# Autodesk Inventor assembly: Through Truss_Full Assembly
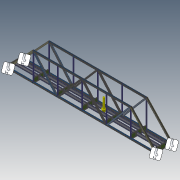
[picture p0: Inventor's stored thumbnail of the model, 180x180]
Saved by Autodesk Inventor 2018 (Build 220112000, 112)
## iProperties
Created: 2018-02
Part Number: Through Truss_Full Assembly
Document SubType Name: Assembly
Designer: STK
Mass: 1.33321e+07 g
Surface Area: 3.07047e+06 cm^2
Volume: 1.69835e+06 cm^3
Density: 7.85 g/cm^3
Author: STK
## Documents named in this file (31)
- D:\SolidWorks\Through Truss\Through Truss_Full Assembly.iam
- D:\SolidWorks\Through Truss\Interior Floor Beam\Interior Floor Beam.iam
- D:\SolidWorks\Through Truss\L1U1\L1U1.iam
- D:\SolidWorks\Through Truss\L2L3.iam
- D:\SolidWorks\Through Truss\L0U1 Plate.ipt
- D:\SolidWorks\Through Truss\L0U1 Plate_Mirrored.ipt
- D:\SolidWorks\Through Truss\L0U1_Connecting Plate.ipt
- D:\SolidWorks\Through Truss\L0U1_Connecting Plate_Mirrored.ipt
- D:\SolidWorks\Through Truss\L2U1_C Channel.ipt
- D:\SolidWorks\Through Truss\L2U1_C Channel_Mirrored.ipt
- D:\SolidWorks\Through Truss\L2U3 C channel.ipt
- D:\SolidWorks\Through Truss\L2U3 C channel_Mirrored.ipt
- D:\SolidWorks\Through Truss\Floor Beam_End\Floor Beam End.iam
- D:\SolidWorks\Through Truss\Rail Girder\Rail Girder.iam
- D:\SolidWorks\Through Truss\Cover Plate_Bearing End.ipt
- D:\SolidWorks\Through Truss\Cover Plate_End Raker End.ipt
- D:\SolidWorks\Through Truss\Cover Plate Top Cords.ipt
- D:\SolidWorks\Through Truss\L2U1_C Channel_MIR.ipt
- D:\SolidWorks\Through Truss\L2U1_C Channel_Mirrored_MIR.ipt
- D:\SolidWorks\Through Truss\L2U3 C channel_MIR.ipt
- D:\SolidWorks\Through Truss\L2U3 C channel_Mirrored_MIR.ipt
- D:\SolidWorks\Through Truss\L0U1 Plate_Mirrored_MIR.ipt
- D:\SolidWorks\Through Truss\L0U1_Connecting Plate_MIR.ipt
- D:\SolidWorks\Through Truss\L0U1_Connecting Plate_Mirrored_MIR.ipt
- D:\SolidWorks\Through Truss\L0U1 Plate_MIR.ipt
- D:\SolidWorks\Through Truss\Cover Plate_Bearing End_MIR.ipt
- D:\SolidWorks\Through Truss\Cover Plate_End Raker End_MIR.ipt
- D:\SolidWorks\Through Truss\Rail Girder\Angle 6 x 6 for rivetting.ipt
- D:\SolidWorks\Through Truss\Rail Girder\Plate For Riveting\Plate For Riveting-02.ipt
- D:\SolidWorks\Through Truss\Rail Girder\Plate For Riveting.ipt
- D:\SolidWorks\Through Truss\Connecting Plate For Riveting.ipt
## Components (175 placed, 29 different names)
1. Interior Floor Beam:1 [sub-assembly] — Mate:5, Mate:6, Flush:2, Flush:5, Flush:6, Mate:7, Flush:8, Flush:9, Mate:9, Flush:10, Mate:39, Mate:54, Mate:56
2. L1U1:1 [sub-assembly] — Flush:6, Flush:7, Mate:7, Flush:13
3. L2L3:1 [sub-assembly] — Flush:9, Mate:9, Flush:10, Flush:11, Flush:12, Mate:11, Mate:13, Flush:30, Mate:27, Flush:31, Mate:33, Mate:60
4. L2L3:2 [sub-assembly] — Flush:11, Mate:10, Flush:12, Mate:14, Flush:14, Flush:15, Mate:23, Mate:24, Mate:26, Flush:28, Mate:61
5. L1U1:2 [sub-assembly] — Mate:12, Mate:13, Flush:13, Flush:18, Flush:19, Mate:59
6. Interior Floor Beam:2 [sub-assembly] — Flush:2, Flush:5, Mate:10, Mate:11, Mate:12, Flush:17, Angle:1, Flush:32, Mate:38, Mate:58
7. L2L3:3 [sub-assembly] — Mate:14, Flush:14, Flush:15, Mate:15, Flush:23, Flush:24, Mate:20, Mate:21, Flush:25, Flush:26, Flush:34, Flush:35, Mate:40
8. Interior Floor Beam:3 [sub-assembly] — Mate:15, Flush:17, Mate:16, Flush:32, Flush:33, Mate:36
9. L1U1:3 [sub-assembly] — Mate:16, Flush:18, Flush:19
10. L2L3:4 [sub-assembly] — Mate:28, Mate:34, Flush:39, Flush:40
11. L2L3:5 [sub-assembly] — Flush:21, Mate:19, Flush:22, Flush:27, Mate:25, Mate:41, Flush:36, Flush:37, Mate:44
12. L0U1 Plate_Mirrored:1 — Flush:21, Mate:19, Flush:22
13. L0U1_Connecting Plate:1 — Flush:23, Flush:24, Mate:20
14. L0U1_Connecting Plate_Mirrored:1 — Mate:21, Flush:25, Flush:26, Mate:35, Mate:43
15. L2U1_C Channel:1 — Mate:24, Flush:27, Mate:25, Flush:29
16. L2U1_C Channel_Mirrored:1 — Mate:26, Flush:28, Flush:29
17. L2U3 C channel:1 — Flush:30, Mate:27, Mate:28
18. L2U3 C channel_Mirrored:1 — Flush:31, Mate:33, Mate:34
19. Floor Beam End:1 [sub-assembly] — Flush:33, Mate:35, Mate:36
20. Cover Plate_Bearing End:1 — Flush:34, Flush:35, Mate:40
21. Cover Plate_End Raker End:1 — Mate:42, Flush:38, Mate:43
22. L0U1 Plate:1 — Mate:41, Flush:36, Flush:37, Mate:42, Flush:38
23. Cover Plate Top Cords:1 — Mate:44, Flush:39, Flush:40
24. Rail Girder:4 [sub-assembly] — Mate:45
25. Rail Girder:5 [sub-assembly]
26. Rail Girder:6 [sub-assembly] — Mate:50, Flush:53, Mate:51, Mate:52, Mate:53
27. L2L3:6 [sub-assembly] — Flush:41, Flush:42
28. L2L3:7 [sub-assembly] — Flush:41, Flush:42, Flush:43, Flush:44, Mate:46, Mate:47
29. L2L3:8 [sub-assembly] — Flush:43, Flush:44, Mate:46
30. L1U1:4 [sub-assembly] — Flush:45, Flush:46
31. L1U1:5 [sub-assembly] — Flush:46, Flush:47, Flush:48
32. L1U1:6 [sub-assembly] — Flush:47, Flush:48
33. L2L3:9 [sub-assembly] — Flush:50, Flush:51
34. L2L3:10 [sub-assembly] — Mate:48
35. Cover Plate Top Cords:2 — Flush:50, Flush:51, Mate:48
36. L2U1_C Channel_MIR:1 — Flush:52
37. L2U1_C Channel_Mirrored_MIR:1 — Flush:52
38. L2U3 C channel_MIR:1
39. L2U3 C channel_Mirrored_MIR:1
40. L0U1 Plate_Mirrored_MIR:1
41. L0U1_Connecting Plate_MIR:1
42. L0U1_Connecting Plate_Mirrored_MIR:1
43. L0U1 Plate_MIR:1
44. Cover Plate_Bearing End_MIR:1
45. Cover Plate_End Raker End_MIR:1
46. Plate For Riveting-02:4 — Flush:57, Flush:58
47. Plate For Riveting-02:3 — Flush:57, Flush:58
48. Plate For Riveting-02:2 — Mate:58, Flush:55, Flush:56
49. Plate For Riveting-02:1 — Mate:54, Mate:56, Mate:57, Flush:55, Flush:56
50. Connecting Plate For Riveting:3
51. Connecting Plate For Riveting:4
52. L1U1:7 [sub-assembly] — Mate:62, Flush:62
53. L2L3:11 [sub-assembly] — Mate:63, Flush:60, Flush:61, Mate:65, Flush:74, Mate:82, Flush:75, Mate:84, Mate:101
54. L2L3:12 [sub-assembly] — Flush:60, Mate:64, Flush:61, Flush:64, Flush:65, Mate:66, Mate:77, Flush:71, Mate:80, Flush:73, Mate:100
55. L1U1:8 [sub-assembly] — Flush:62, Mate:65, Flush:63, Flush:68, Flush:69, Mate:102
56. Interior Floor Beam:4 [sub-assembly] — Mate:63, Mate:64, Flush:63, Flush:66, Flush:67, Angle:2, Mate:86, Mate:99
57. L2L3:13 [sub-assembly] — Flush:64, Flush:65, Mate:66, Mate:67, Mate:71, Mate:72, Mate:73, Mate:74, Mate:75, Mate:76, Mate:87, Flush:79, Flush:80
58. Interior Floor Beam:5 [sub-assembly] — Flush:66, Flush:67, Mate:67, Flush:70, Mate:85, Flush:77
59. L1U1:9 [sub-assembly] — Flush:68, Flush:69, Flush:70
60. L2L3:14 [sub-assembly] — Mate:81, Mate:83, Flush:82, Flush:83
61. L2L3:15 [sub-assembly] — Mate:68, Mate:69, Mate:70, Mate:78, Mate:79, Mate:90, Mate:91, Mate:92, Mate:93
62. L0U1 Plate_Mirrored:2 — Mate:68, Mate:69, Mate:70
63. L0U1_Connecting Plate:2 — Mate:71, Mate:72, Mate:73
64. L0U1_Connecting Plate_Mirrored:2 — Mate:74, Mate:75, Mate:76, Flush:76, Mate:88
65. L2U1_C Channel:2 — Mate:78, Mate:79, Flush:71, Flush:72
66. L2U1_C Channel_Mirrored:2 — Flush:72, Mate:80, Flush:73
67. L2U3 C channel:2 — Mate:81, Flush:74, Mate:82
68. L2U3 C channel_Mirrored:2 — Mate:83, Flush:75, Mate:84
69. Floor Beam End:2 [sub-assembly] — Mate:85, Flush:76, Flush:77
70. Cover Plate_Bearing End:2 — Mate:87, Flush:79, Flush:80
71. Cover Plate_End Raker End:2 — Mate:88, Flush:81, Mate:89
72. L0U1 Plate:2 — Flush:81, Mate:89, Mate:90, Mate:91, Mate:92
73. Cover Plate Top Cords:3 — Flush:82, Flush:83, Mate:93
74. Rail Girder:8 [sub-assembly] — Flush:84
75. Rail Girder:9 [sub-assembly]
76. Rail Girder:10 [sub-assembly] — Flush:96, Mate:97, Flush:97, Mate:98, Flush:99
77. L2L3:16 [sub-assembly] — Flush:85, Flush:86
78. L2L3:17 [sub-assembly] — Flush:85, Flush:86, Mate:94, Flush:87, Flush:88, Mate:95
79. L2L3:18 [sub-assembly] — Mate:94, Flush:87, Flush:88
80. L1U1:10 [sub-assembly] — Flush:89, Flush:90
81. L1U1:11 [sub-assembly] — Flush:90, Flush:91, Flush:92
82. L1U1:12 [sub-assembly] — Flush:91, Flush:92
83. L2L3:19 [sub-assembly] — Flush:93, Flush:94
84. L2L3:20 [sub-assembly] — Mate:96
85. Cover Plate Top Cords:4 — Mate:96, Flush:93, Flush:94
86. L2U1_C Channel_MIR:2 — Flush:95
87. L2U1_C Channel_Mirrored_MIR:2 — Flush:95
88. L2U3 C channel_MIR:2
89. L2U3 C channel_Mirrored_MIR:2
90. L0U1 Plate_Mirrored_MIR:2
91. L0U1_Connecting Plate_MIR:2
92. L0U1_Connecting Plate_Mirrored_MIR:2
93. L0U1 Plate_MIR:2
94. Cover Plate_Bearing End_MIR:2
95. Cover Plate_End Raker End_MIR:2
96. Plate For Riveting-02:13 — Flush:100, Flush:101, Flush:102
97. Plate For Riveting-02:14 — Flush:101, Flush:102, Mate:99
98. Plate For Riveting-02:15 — Flush:103, Flush:104
99. Plate For Riveting-02:16 — Flush:103, Flush:104
100. Connecting Plate For Riveting:6
101. Connecting Plate For Riveting:7
102. Rail Girder:1 [sub-assembly] — Mate:37, Mate:38, Mate:39, Mate:57
103. Rail Girder:2 [sub-assembly]
104. Rail Girder:3 [sub-assembly]
105. Plate For Riveting-02:6
106. Plate For Riveting-02:5
107. Plate For Riveting-02:7
108. Plate For Riveting-02:8
109. Plate For Riveting-02:9
110. Plate For Riveting-02:10
111. Plate For Riveting-02:11
112. Plate For Riveting-02:12
113. Angle 6 x 6 for rivetting:1 — Mate:50, Flush:53, Mate:51, Flush:54
114. Angle 6 x 6 for rivetting:7
115. Angle 6 x 6 for rivetting:3
116. Angle 6 x 6 for rivetting:5 — Flush:59
117. Angle 6 x 6 for rivetting:2 — Mate:52, Mate:53, Flush:54
118. Angle 6 x 6 for rivetting:8
119. Angle 6 x 6 for rivetting:6 — Flush:59
120. Angle 6 x 6 for rivetting:4
121. Angle 6 x 6 for rivetting:9
122. Angle 6 x 6 for rivetting:10
123. Angle 6 x 6 for rivetting:11
124. Angle 6 x 6 for rivetting:12
125. Angle 6 x 6 for rivetting:13
126. Angle 6 x 6 for rivetting:14
127. Angle 6 x 6 for rivetting:15
128. Angle 6 x 6 for rivetting:16
129. Angle 6 x 6 for rivetting:17
130. Angle 6 x 6 for rivetting:18
131. Angle 6 x 6 for rivetting:19
132. Angle 6 x 6 for rivetting:20
133. Angle 6 x 6 for rivetting:21
134. Angle 6 x 6 for rivetting:22
135. Angle 6 x 6 for rivetting:23
136. Angle 6 x 6 for rivetting:24
137. Connecting Plate For Riveting:1 — Mate:59, Mate:60, Mate:61
138. Connecting Plate For Riveting:2
139. Rail Girder:7 [sub-assembly] — Mate:86, Flush:78, Flush:100
140. Rail Girder:11 [sub-assembly]
141. Rail Girder:12 [sub-assembly]
142. Plate For Riveting-02:17
143. Plate For Riveting-02:18
144. Plate For Riveting-02:21
145. Plate For Riveting-02:22
146. Plate For Riveting-02:19
147. Plate For Riveting-02:20
148. Plate For Riveting-02:23
149. Plate For Riveting-02:24
150. Angle 6 x 6 for rivetting:25 — Flush:96, Mate:97, Flush:97, Flush:98
151. Angle 6 x 6 for rivetting:26
152. Angle 6 x 6 for rivetting:27
153. Angle 6 x 6 for rivetting:28 — Flush:105
154. Angle 6 x 6 for rivetting:29 — Flush:98, Mate:98, Flush:99
155. Angle 6 x 6 for rivetting:30
156. Angle 6 x 6 for rivetting:31 — Flush:105
157. Angle 6 x 6 for rivetting:32
158. Angle 6 x 6 for rivetting:33
159. Angle 6 x 6 for rivetting:34
160. Angle 6 x 6 for rivetting:35
161. Angle 6 x 6 for rivetting:36
162. Angle 6 x 6 for rivetting:37
163. Angle 6 x 6 for rivetting:38
164. Angle 6 x 6 for rivetting:39
165. Angle 6 x 6 for rivetting:40
166. Angle 6 x 6 for rivetting:41
167. Angle 6 x 6 for rivetting:42
168. Angle 6 x 6 for rivetting:43
169. Angle 6 x 6 for rivetting:44
170. Angle 6 x 6 for rivetting:45
171. Angle 6 x 6 for rivetting:46
172. Angle 6 x 6 for rivetting:47
173. Angle 6 x 6 for rivetting:48
174. Connecting Plate For Riveting:5 — Mate:100, Mate:101, Mate:102
175. Connecting Plate For Riveting:8
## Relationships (189: Flush 99, Mate 88, Angle 2)
- Mate:5: Interior Floor Beam:1
- Mate:6: Interior Floor Beam:1
- Flush:2: Interior Floor Beam:1 ↔ Interior Floor Beam:2
- Flush:5: Interior Floor Beam:1 ↔ Interior Floor Beam:2
- Flush:6: Interior Floor Beam:1 ↔ L1U1:1
- Flush:7: L1U1:1
- Mate:7: Interior Floor Beam:1 ↔ L1U1:1
- Flush:8: Interior Floor Beam:1
- Flush:9: Interior Floor Beam:1 ↔ L2L3:1
- Mate:9: Interior Floor Beam:1 ↔ L2L3:1
- Flush:10: Interior Floor Beam:1 ↔ L2L3:1
- Flush:11: L2L3:1 ↔ L2L3:2
- Mate:10: L2L3:2 ↔ Interior Floor Beam:2
- Flush:12: L2L3:1 ↔ L2L3:2
- Mate:11: L2L3:1 ↔ Interior Floor Beam:2
- Mate:12: L1U1:2 ↔ Interior Floor Beam:2
- Mate:13: L2L3:1 ↔ L1U1:2
- Flush:13: L1U1:1 ↔ L1U1:2
- Mate:14: L2L3:2 ↔ L2L3:3
- Flush:14: L2L3:2 ↔ L2L3:3
- Flush:15: L2L3:2 ↔ L2L3:3
- Mate:15: L2L3:3 ↔ Interior Floor Beam:3
- Flush:17: Interior Floor Beam:2 ↔ Interior Floor Beam:3
- Mate:16: Interior Floor Beam:3 ↔ L1U1:3
- Flush:18: L1U1:2 ↔ L1U1:3
- Flush:19: L1U1:2 ↔ L1U1:3
- Flush:21: L2L3:5 ↔ L0U1 Plate_Mirrored:1
- Mate:19: L2L3:5 ↔ L0U1 Plate_Mirrored:1
- Flush:22: L2L3:5 ↔ L0U1 Plate_Mirrored:1
- Flush:23: L2L3:3 ↔ L0U1_Connecting Plate:1
- Flush:24: L2L3:3 ↔ L0U1_Connecting Plate:1
- Mate:20: L2L3:3 ↔ L0U1_Connecting Plate:1
- Mate:21: L2L3:3 ↔ L0U1_Connecting Plate_Mirrored:1
- Flush:25: L2L3:3 ↔ L0U1_Connecting Plate_Mirrored:1
- Flush:26: L2L3:3 ↔ L0U1_Connecting Plate_Mirrored:1
- Mate:23: L2L3:2
- Angle:1: Interior Floor Beam:2
- Mate:24: L2L3:2 ↔ L2U1_C Channel:1
- Flush:27: L2L3:5 ↔ L2U1_C Channel:1
- Mate:25: L2L3:5 ↔ L2U1_C Channel:1
- Mate:26: L2L3:2 ↔ L2U1_C Channel_Mirrored:1
- Flush:28: L2L3:2 ↔ L2U1_C Channel_Mirrored:1
- Flush:29: L2U1_C Channel:1 ↔ L2U1_C Channel_Mirrored:1
- Flush:30: L2L3:1 ↔ L2U3 C channel:1
- Mate:27: L2L3:1 ↔ L2U3 C channel:1
- Mate:28: L2L3:4 ↔ L2U3 C channel:1
- Flush:31: L2L3:1 ↔ L2U3 C channel_Mirrored:1
- Mate:33: L2L3:1 ↔ L2U3 C channel_Mirrored:1
- Mate:34: L2L3:4 ↔ L2U3 C channel_Mirrored:1
- Flush:32: Interior Floor Beam:2 ↔ Interior Floor Beam:3
- Flush:33: Interior Floor Beam:3 ↔ Floor Beam End:1
- Mate:35: L0U1_Connecting Plate_Mirrored:1 ↔ Floor Beam End:1
- Mate:36: Interior Floor Beam:3 ↔ Floor Beam End:1
- Mate:37: Rail Girder:1
- Mate:38: Interior Floor Beam:2 ↔ Rail Girder:1
- Mate:39: Interior Floor Beam:1 ↔ Rail Girder:1
- Flush:34: L2L3:3 ↔ Cover Plate_Bearing End:1
- Flush:35: L2L3:3 ↔ Cover Plate_Bearing End:1
- Mate:40: L2L3:3 ↔ Cover Plate_Bearing End:1
- Mate:41: L2L3:5 ↔ L0U1 Plate:1
- Flush:36: L2L3:5 ↔ L0U1 Plate:1
- Flush:37: L2L3:5 ↔ L0U1 Plate:1
- Mate:42: Cover Plate_End Raker End:1 ↔ L0U1 Plate:1
- Flush:38: Cover Plate_End Raker End:1 ↔ L0U1 Plate:1
- Mate:43: L0U1_Connecting Plate_Mirrored:1 ↔ Cover Plate_End Raker End:1
- Mate:44: L2L3:5 ↔ Cover Plate Top Cords:1
- Flush:39: L2L3:4 ↔ Cover Plate Top Cords:1
- Flush:40: L2L3:4 ↔ Cover Plate Top Cords:1
- Mate:45: Rail Girder:4
- Flush:41: L2L3:6 ↔ L2L3:7
- Flush:42: L2L3:6 ↔ L2L3:7
- Flush:43: L2L3:7 ↔ L2L3:8
- Flush:44: L2L3:7 ↔ L2L3:8
- Mate:46: L2L3:7 ↔ L2L3:8
- Mate:47: L2L3:7
- Flush:45: L1U1:4
- Flush:46: L1U1:4 ↔ L1U1:5
- Flush:47: L1U1:5 ↔ L1U1:6
- Flush:48: L1U1:5 ↔ L1U1:6
- Flush:50: L2L3:9 ↔ Cover Plate Top Cords:2
- Flush:51: L2L3:9 ↔ Cover Plate Top Cords:2
- Mate:48: L2L3:10 ↔ Cover Plate Top Cords:2
- Flush:52: L2U1_C Channel_MIR:1 ↔ L2U1_C Channel_Mirrored_MIR:1
- Mate:50: Rail Girder:6 ↔ Angle 6 x 6 for rivetting:1
- Flush:53: Rail Girder:6 ↔ Angle 6 x 6 for rivetting:1
- Mate:51: Rail Girder:6 ↔ Angle 6 x 6 for rivetting:1
- Mate:52: Rail Girder:6 ↔ Angle 6 x 6 for rivetting:2
- Mate:53: Rail Girder:6 ↔ Angle 6 x 6 for rivetting:2
- Flush:54: Angle 6 x 6 for rivetting:1 ↔ Angle 6 x 6 for rivetting:2
- Mate:54: Interior Floor Beam:1 ↔ Plate For Riveting-02:1
- Mate:56: Interior Floor Beam:1 ↔ Plate For Riveting-02:1
- Mate:57: Plate For Riveting-02:1 ↔ Rail Girder:1
- Mate:58: Interior Floor Beam:2 ↔ Plate For Riveting-02:2
- Flush:55: Plate For Riveting-02:2 ↔ Plate For Riveting-02:1
- Flush:56: Plate For Riveting-02:2 ↔ Plate For Riveting-02:1
- Flush:57: Plate For Riveting-02:4 ↔ Plate For Riveting-02:3
- Flush:58: Plate For Riveting-02:4 ↔ Plate For Riveting-02:3
- Flush:59: Angle 6 x 6 for rivetting:5 ↔ Angle 6 x 6 for rivetting:6
- Mate:59: L1U1:2 ↔ Connecting Plate For Riveting:1
- Mate:60: L2L3:1 ↔ Connecting Plate For Riveting:1
- Mate:61: L2L3:2 ↔ Connecting Plate For Riveting:1
- Mate:62: L1U1:7
- Mate:63: L2L3:11 ↔ Interior Floor Beam:4
- Flush:60: L2L3:11 ↔ L2L3:12
- Mate:64: L2L3:12 ↔ Interior Floor Beam:4
- Flush:61: L2L3:11 ↔ L2L3:12
- Flush:62: L1U1:7 ↔ L1U1:8
- Mate:65: L2L3:11 ↔ L1U1:8
- Flush:63: L1U1:8 ↔ Interior Floor Beam:4
- Flush:64: L2L3:12 ↔ L2L3:13
- Flush:65: L2L3:12 ↔ L2L3:13
- Mate:66: L2L3:12 ↔ L2L3:13
- Flush:66: Interior Floor Beam:4 ↔ Interior Floor Beam:5
- Flush:67: Interior Floor Beam:4 ↔ Interior Floor Beam:5
- Mate:67: L2L3:13 ↔ Interior Floor Beam:5
- Flush:68: L1U1:8 ↔ L1U1:9
- Flush:69: L1U1:8 ↔ L1U1:9
- Flush:70: Interior Floor Beam:5 ↔ L1U1:9
- Mate:68: L2L3:15 ↔ L0U1 Plate_Mirrored:2
- Mate:69: L2L3:15 ↔ L0U1 Plate_Mirrored:2
- Mate:70: L2L3:15 ↔ L0U1 Plate_Mirrored:2
- Mate:71: L2L3:13 ↔ L0U1_Connecting Plate:2
- Mate:72: L2L3:13 ↔ L0U1_Connecting Plate:2
- Mate:73: L2L3:13 ↔ L0U1_Connecting Plate:2
- Mate:74: L2L3:13 ↔ L0U1_Connecting Plate_Mirrored:2
- Mate:75: L2L3:13 ↔ L0U1_Connecting Plate_Mirrored:2
- Mate:76: L2L3:13 ↔ L0U1_Connecting Plate_Mirrored:2
- Angle:2: Interior Floor Beam:4
- Mate:77: L2L3:12
- Mate:78: L2L3:15 ↔ L2U1_C Channel:2
- Mate:79: L2L3:15 ↔ L2U1_C Channel:2
- Flush:71: L2L3:12 ↔ L2U1_C Channel:2
- Flush:72: L2U1_C Channel:2 ↔ L2U1_C Channel_Mirrored:2
- Mate:80: L2L3:12 ↔ L2U1_C Channel_Mirrored:2
- Flush:73: L2L3:12 ↔ L2U1_C Channel_Mirrored:2
- Mate:81: L2L3:14 ↔ L2U3 C channel:2
- Flush:74: L2L3:11 ↔ L2U3 C channel:2
- Mate:82: L2L3:11 ↔ L2U3 C channel:2
- Mate:83: L2L3:14 ↔ L2U3 C channel_Mirrored:2
- Flush:75: L2L3:11 ↔ L2U3 C channel_Mirrored:2
- Mate:84: L2L3:11 ↔ L2U3 C channel_Mirrored:2
- Mate:85: Interior Floor Beam:5 ↔ Floor Beam End:2
- Flush:76: L0U1_Connecting Plate_Mirrored:2 ↔ Floor Beam End:2
- Flush:77: Interior Floor Beam:5 ↔ Floor Beam End:2
- Mate:86: Interior Floor Beam:4 ↔ Rail Girder:7
- Flush:78: Rail Girder:7
- Mate:87: L2L3:13 ↔ Cover Plate_Bearing End:2
- Flush:79: L2L3:13 ↔ Cover Plate_Bearing End:2
- Flush:80: L2L3:13 ↔ Cover Plate_Bearing End:2
- Mate:88: L0U1_Connecting Plate_Mirrored:2 ↔ Cover Plate_End Raker End:2
- Flush:81: Cover Plate_End Raker End:2 ↔ L0U1 Plate:2
- Mate:89: Cover Plate_End Raker End:2 ↔ L0U1 Plate:2
- Mate:90: L2L3:15 ↔ L0U1 Plate:2
- Mate:91: L2L3:15 ↔ L0U1 Plate:2
- Mate:92: L2L3:15 ↔ L0U1 Plate:2
- Flush:82: L2L3:14 ↔ Cover Plate Top Cords:3
- Flush:83: L2L3:14 ↔ Cover Plate Top Cords:3
- Mate:93: L2L3:15 ↔ Cover Plate Top Cords:3
- Flush:84: Rail Girder:8
- Flush:85: L2L3:16 ↔ L2L3:17
- Flush:86: L2L3:16 ↔ L2L3:17
- Mate:94: L2L3:17 ↔ L2L3:18
- Flush:87: L2L3:17 ↔ L2L3:18
- Flush:88: L2L3:17 ↔ L2L3:18
- Mate:95: L2L3:17
- Flush:89: L1U1:10
- Flush:90: L1U1:10 ↔ L1U1:11
- Flush:91: L1U1:11 ↔ L1U1:12
- Flush:92: L1U1:11 ↔ L1U1:12
- Mate:96: L2L3:20 ↔ Cover Plate Top Cords:4
- Flush:93: L2L3:19 ↔ Cover Plate Top Cords:4
- Flush:94: L2L3:19 ↔ Cover Plate Top Cords:4
- Flush:95: L2U1_C Channel_MIR:2 ↔ L2U1_C Channel_Mirrored_MIR:2
- Flush:96: Rail Girder:10 ↔ Angle 6 x 6 for rivetting:25
- Mate:97: Rail Girder:10 ↔ Angle 6 x 6 for rivetting:25
- Flush:97: Rail Girder:10 ↔ Angle 6 x 6 for rivetting:25
- Flush:98: Angle 6 x 6 for rivetting:25 ↔ Angle 6 x 6 for rivetting:29
- Mate:98: Rail Girder:10 ↔ Angle 6 x 6 for rivetting:29
- Flush:99: Rail Girder:10 ↔ Angle 6 x 6 for rivetting:29
- Flush:100: Plate For Riveting-02:13 ↔ Rail Girder:7
- Flush:101: Plate For Riveting-02:13 ↔ Plate For Riveting-02:14
- Flush:102: Plate For Riveting-02:13 ↔ Plate For Riveting-02:14
- Mate:99: Interior Floor Beam:4 ↔ Plate For Riveting-02:14
- Flush:103: Plate For Riveting-02:15 ↔ Plate For Riveting-02:16
- Flush:104: Plate For Riveting-02:15 ↔ Plate For Riveting-02:16
- Flush:105: Angle 6 x 6 for rivetting:28 ↔ Angle 6 x 6 for rivetting:31
- Mate:100: L2L3:12 ↔ Connecting Plate For Riveting:5
- Mate:101: L2L3:11 ↔ Connecting Plate For Riveting:5
- Mate:102: L1U1:8 ↔ Connecting Plate For Riveting:5
## Named parameters: sa_0 = 1.03005e+08 mm, sa_1 = 4445 mm, sa_2 = 0, sa_3 = 0
